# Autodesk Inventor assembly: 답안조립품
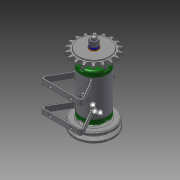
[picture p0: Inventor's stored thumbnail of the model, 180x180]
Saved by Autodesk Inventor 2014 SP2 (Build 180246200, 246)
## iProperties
Created: 2016-03
Part Number: 답안조립품
Document SubType Name: Assembly
Designer: 이도윤
Author: 이도윤
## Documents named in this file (15)
- C:\Users\201-13\Desktop\460307V1016\답안조립품.iam
- C:\Users\201-13\Desktop\460307V1016\본체.ipt
- C:\Users\201-13\Desktop\460307V1016\커버.ipt
- C:\Users\201-13\Desktop\460307V1016\축.ipt
- C:\Users\201-13\Desktop\460307V1016\키 3 x 3 x 12.ipt
- C:\Users\201-13\Desktop\460307V1016\베어링 15 x 32 x 9.ipt
- C:\Users\201-13\Desktop\460307V1016\V벨트풀리.ipt
- C:\Users\201-13\Desktop\460307V1016\스프링와셔 8.ipt
- C:\Users\201-13\Desktop\460307V1016\와셔 8x17.ipt
- C:\Users\201-13\Desktop\460307V1016\너트 M 8.ipt
- C:\Users\201-13\Desktop\460307V1016\스프로킷.ipt
- C:\Users\201-13\Desktop\460307V1016\오일 실 15 25 7.ipt
- C:\Users\201-13\Desktop\460307V1016\볼트 M4 x 12.ipt
- C:\Users\201-13\Desktop\460307V1016\니플 M 6 x 0.75.ipt
- C:\Users\201-13\Desktop\460307V1016\볼트 M 6 x 8.ipt
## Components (11 placed, 3 different names)
1. KS B 2023 6002 - 15 x 32 x 9:1
2. KS B 2023 6002 - 15 x 32 x 9:2
3. V벨트풀리:1
4. ISO 4762 M4 x 12:2
5. ISO 4762 M4 x 12:3
6. ISO 4762 M4 x 12:4
7. ISO 4762 M4 x 12:5
8. ISO 4762 M4 x 12:1
9. ISO 4762 M4 x 12:6
10. ISO 4762 M4 x 12:7
11. ISO 4762 M4 x 12:8
